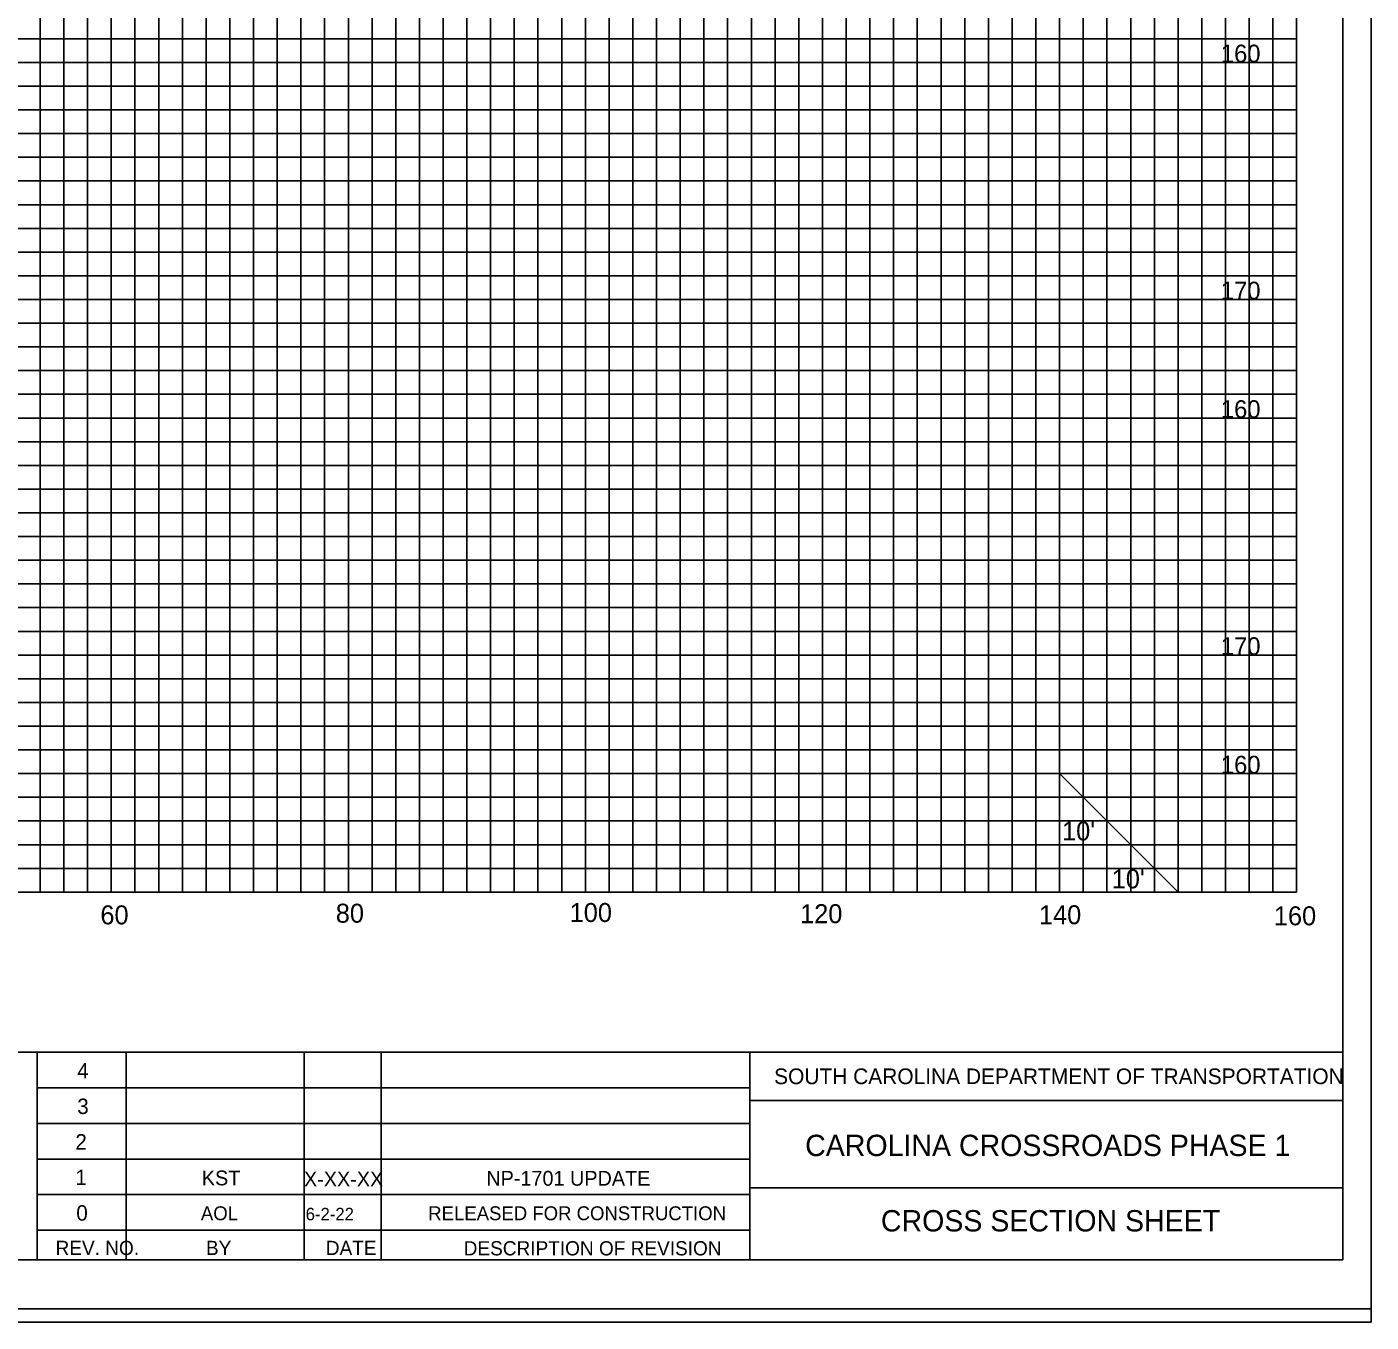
# Model space of a CAD drawing. Extents: x 967 to 1326, y 964 to 2864.
# Drawn here: x 1212.9 to 1326.3, y 1243.7 to 1353 of the extents above; entities that cross this region are included whole.
import ezdxf

# ---------------------------------------------------------------- set-up
doc = ezdxf.new("R2010")
doc.units = 0
for name, color, linetype in [('Default', 7, 'Continuous'), ('RD_EX_RW', 7, 'Continuous'), ('RD_PD_Final_TX', 7, 'Continuous'), ('RD_SHT_ShtClip', 7, 'Continuous'), ('RD_XS_TX_Elev_PR', 7, 'Continuous'), ('RD_XS_TX_ShdSlope', 7, 'Continuous'), ('RD_XS_TX_Slope', 7, 'Continuous')]:
    doc.layers.add(name, color=color, linetype=linetype)

msp = doc.modelspace()

# ---------------------------------------------------------------- linework, layer by layer
at = {"layer": 'RD_EX_RW'}
for p, q in [((1220, 1280), (1220, 1450)), ((1230, 1280), (1230, 1450)), ((1240, 1280), (1240, 1450)), ((1250, 1280), (1250, 1450)), ((1260, 1280), (1260, 1450)), ((1270, 1280), (1270, 1450)), ((1280, 1280), (1280, 1450)), ((1290, 1280), (1290, 1450)), ((1300, 1280), (1300, 1450)), ((1310, 1280), (1310, 1450)), ((1320, 1280), (1320, 1450)), ((1000, 1350), (1320, 1350)), ((1000, 1340), (1320, 1340)), ((1000, 1330), (1320, 1330)), ((1000, 1320), (1320, 1320)), ((1000, 1310), (1320, 1310)), ((1000, 1300), (1320, 1300)), ((1000, 1290), (1320, 1290)), ((1000, 1280), (1320, 1280))]:
    msp.add_line(p, q, dxfattribs=at)
at = {"layer": 'RD_PD_Final_TX'}
for p, q in [((1323.89, 1458.46), (1323.89, 1248.98)), ((996.11, 1266.49), (1323.89, 1266.49)), ((1213.76, 1248.94), (1213.76, 1266.49)), ((1221.26, 1248.95), (1221.26, 1266.48)), ((1236.26, 1248.95), (1236.26, 1266.48)), ((1242.76, 1248.95), (1242.76, 1266.48)), ((1273.88, 1248.98), (1273.88, 1266.49)), ((1213.76, 1263.48), (1273.88, 1263.48)), ((1323.93, 1262.43), (1273.88, 1262.43)), ((1213.76, 1260.48), (1273.88, 1260.48)), ((1213.76, 1257.48), (1273.88, 1257.48)), ((1213.76, 1254.48), (1273.88, 1254.48)), ((1323.89, 1255.04), (1273.88, 1255.04)), ((1213.76, 1251.48), (1273.88, 1251.48)), ((1323.89, 1248.98), (996.11, 1248.98))]:
    msp.add_line(p, q, dxfattribs=at)
at = {"layer": 'RD_SHT_ShtClip'}
for p, q in [((1214, 1280), (1214, 1450)), ((1216, 1280), (1216, 1450)), ((1218, 1280), (1218, 1450)), ((1222, 1280), (1222, 1450)), ((1224, 1280), (1224, 1450)), ((1226, 1280), (1226, 1450)), ((1228, 1280), (1228, 1450)), ((1232, 1280), (1232, 1450)), ((1234, 1280), (1234, 1450)), ((1236, 1280), (1236, 1450)), ((1238, 1280), (1238, 1450)), ((1242, 1280), (1242, 1450)), ((1244, 1280), (1244, 1450)), ((1246, 1280), (1246, 1450)), ((1248, 1280), (1248, 1450)), ((1252, 1280), (1252, 1450)), ((1254, 1280), (1254, 1450)), ((1256, 1280), (1256, 1450)), ((1258, 1280), (1258, 1450)), ((1262, 1280), (1262, 1450)), ((1264, 1280), (1264, 1450)), ((1266, 1280), (1266, 1450)), ((1268, 1280), (1268, 1450)), ((1272, 1280), (1272, 1450)), ((1274, 1280), (1274, 1450)), ((1276, 1280), (1276, 1450)), ((1278, 1280), (1278, 1450)), ((1282, 1280), (1282, 1450)), ((1284, 1280), (1284, 1450)), ((1286, 1280), (1286, 1450)), ((1288, 1280), (1288, 1450)), ((1292, 1280), (1292, 1450)), ((1294, 1280), (1294, 1450)), ((1296, 1280), (1296, 1450)), ((1298, 1280), (1298, 1450)), ((1302, 1280), (1302, 1450)), ((1304, 1280), (1304, 1450)), ((1306, 1280), (1306, 1450)), ((1308, 1280), (1308, 1450)), ((1312, 1280), (1312, 1450)), ((1314, 1280), (1314, 1450)), ((1316, 1280), (1316, 1450)), ((1318, 1280), (1318, 1450)), ((1000, 1352), (1320, 1352)), ((1000, 1348), (1320, 1348)), ((1000, 1346), (1320, 1346)), ((1000, 1344), (1320, 1344)), ((1000, 1342), (1320, 1342)), ((1000, 1338), (1320, 1338)), ((1000, 1336), (1320, 1336)), ((1000, 1334), (1320, 1334)), ((1000, 1332), (1320, 1332)), ((1000, 1328), (1320, 1328)), ((1000, 1326), (1320, 1326)), ((1000, 1324), (1320, 1324)), ((1000, 1322), (1320, 1322)), ((1000, 1318), (1320, 1318)), ((1000, 1316), (1320, 1316)), ((1000, 1314), (1320, 1314)), ((1000, 1312), (1320, 1312)), ((1000, 1308), (1320, 1308)), ((1000, 1306), (1320, 1306)), ((1000, 1304), (1320, 1304)), ((1000, 1302), (1320, 1302)), ((1000, 1298), (1320, 1298)), ((1000, 1296), (1320, 1296)), ((1000, 1294), (1320, 1294)), ((1000, 1292), (1320, 1292)), ((1000, 1288), (1320, 1288)), ((1000, 1286), (1320, 1286)), ((1000, 1284), (1320, 1284)), ((1000, 1282), (1320, 1282))]:
    msp.add_line(p, q, dxfattribs=at)
at = {"layer": 'RD_XS_TX_Elev_PR'}
for points in [[(967.41, 1243.72), (1326.28, 1243.72), (1326.28, 1463.72), (967.41, 1463.72)], [(988.52, 1244.84), (1326.28, 1244.84), (1326.28, 1462.6), (988.52, 1462.6)]]:
    msp.add_lwpolyline(points, close=True, dxfattribs=at)
at = {"layer": 'RD_XS_TX_Slope'}
msp.add_line((1300, 1290), (1310, 1280), dxfattribs=at)

# ---------------------------------------------------------------- texts
at = {"layer": 'Default'}
for s, p in [('160', (1313.61, 1350)), ('170', (1313.61, 1330)), ('160', (1313.61, 1320)), ('170', (1313.61, 1300)), ('160', (1313.61, 1290))]:
    msp.add_text(s, height=1.5, dxfattribs=at).set_placement(p)
for s, p in [('KST', (1227.64, 1255.26)), ('X-XX-XX', (1236.26, 1255.17)), ('NP-1701 UPDATE', (1251.64, 1255.23))]:
    msp.add_text(s, height=1.25, rotation=360, dxfattribs=at).set_placement(p)
at = {"layer": 'RD_XS_TX_ShdSlope'}
for s, height, p in [('AOL', 1.17, (1227.56, 1252.32)), ('6-2-22', 1.053, (1236.4, 1252.31)), ('RELEASED FOR CONSTRUCTION', 1.17, (1246.74, 1252.32))]:
    msp.add_text(s, height=height, dxfattribs=at).set_placement(p)
at = {"layer": 'RD_XS_TX_Slope'}
for s, height, p in [("10'", 1.6, (1300.21, 1284.36)), ("10'", 1.6, (1304.4, 1280.32)), ('60', 1.6, (1219.08, 1277.28)), ('80', 1.6, (1238.94, 1277.42)), ('100', 1.6, (1258.67, 1277.48)), ('120', 1.6, (1278.11, 1277.38)), ('140', 1.6, (1298.26, 1277.29)), ('160', 1.6, (1318.08, 1277.2)), ('4', 1.3, (1217.13, 1264.28)), ('SOUTH CAROLINA DEPARTMENT OF TRANSPORTATION', 1.32, (1275.92, 1263.8)), ('3', 1.3, (1217.13, 1261.28)), ('2', 1.3, (1216.97, 1258.28)), ('1', 1.3, (1216.97, 1255.28)), ('0', 1.3, (1217.05, 1252.28)), ('REV. NO.', 1.2, (1215.3, 1249.38)), ('BY', 1.2, (1227.99, 1249.38)), ('DATE', 1.2, (1238.1, 1249.38)), ('DESCRIPTION OF REVISION', 1.2, (1249.73, 1249.35))]:
    msp.add_text(s, height=height, dxfattribs=at).set_placement(p)
for s, p in [('CAROLINA CROSSROADS PHASE 1', (1278.54, 1257.73)), ('CROSS SECTION SHEET', (1284.93, 1251.37))]:
    msp.add_text(s, height=1.8, rotation=0, dxfattribs=at).set_placement(p)

doc.saveas('drawing.dxf')
